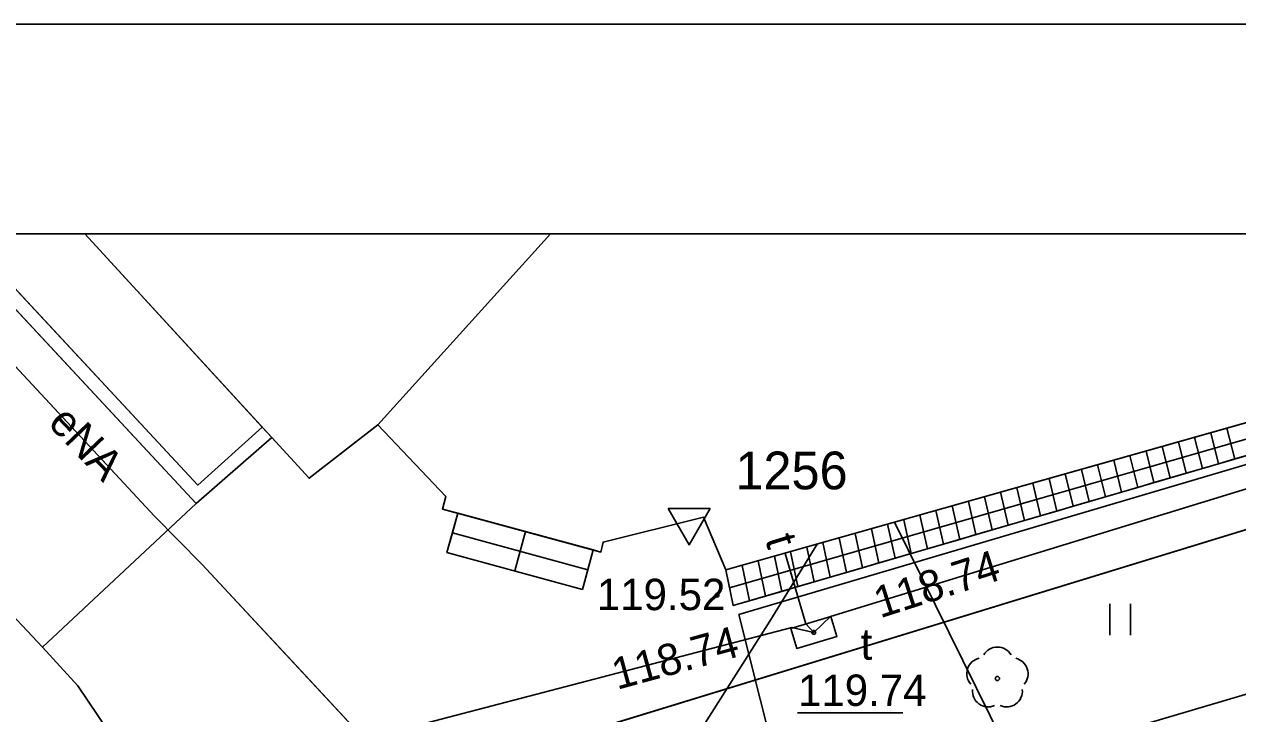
# Model space of a CAD drawing. Extents: x 6432121 to 6432331, y 5662538 to 5662686.
# Drawn here: x 6432164.71 to 6432193.67, y 5662669.6 to 5662686.05 of the extents above; entities that cross this region are included whole.
import ezdxf

# ---------------------------------------------------------------- set-up
doc = ezdxf.new("R2010")
doc.units = 0
for name, color, linetype in [('Warstwa 1', 7, 'Continuous'), ('Warstwa 10', 7, 'Continuous'), ('Warstwa 11', 7, 'Continuous'), ('Warstwa 12', 7, 'Continuous'), ('Warstwa 13', 7, 'Continuous'), ('Warstwa 14', 7, 'Continuous'), ('Warstwa 15', 7, 'Continuous'), ('Warstwa 2', 7, 'Continuous'), ('Warstwa 25', 7, 'Continuous'), ('Warstwa 36', 7, 'Continuous'), ('Warstwa 4', 7, 'Continuous'), ('Warstwa 5', 7, 'Continuous'), ('Warstwa 6', 7, 'Continuous'), ('Warstwa 61', 7, 'Continuous'), ('Warstwa 63', 7, 'Continuous'), ('Warstwa 9', 7, 'Continuous')]:
    doc.layers.add(name, color=color, linetype=linetype)

msp = doc.modelspace()

# ---------------------------------------------------------------- linework, layer by layer
at = {"layer": 'Warstwa 1'}
msp.add_line((6432136.78, 5662656.51), (6432207.04, 5662678.03), dxfattribs=at)
msp.add_line((6432136.78, 5662656.51), (6432207.04, 5662678.03), dxfattribs=at)
msp.add_lwpolyline([(6432166.159, 5662681.053), (6432171.511, 5662675.224), (6432173.15, 5662676.497), (6432174.775, 5662674.789), (6432174.698, 5662674.488), (6432178.474, 5662673.461), (6432178.529, 5662673.7), (6432180.921, 5662674.296), (6432181.459, 5662673.034), (6432202.03, 5662678.854), (6432201.441, 5662681.053)], dxfattribs=at)
at = {"layer": 'Warstwa 10'}
msp.add_lwpolyline([(6432178.835, 5662663.483), (6432175.942, 5662663.535), (6432175.535, 5662666.115), (6432173.894, 5662667.86), (6432171.424, 5662670.517), (6432168.955, 5662673.173), (6432167.819, 5662674.322), (6432163.861, 5662678.574), (6432161.552, 5662681.053)], dxfattribs=at)
at = {"layer": 'Warstwa 11'}
msp.add_circle((6432187.938, 5662670.445), 0.05, dxfattribs=at)
for centre, start, end in [((6432187.938, 5662670.82), 30.1471, 149.8529), ((6432187.581, 5662670.561), 102.1471, 221.8529), ((6432188.295, 5662670.561), 318.1471, 77.8529), ((6432187.718, 5662670.142), 174.1471, 293.8529), ((6432188.158, 5662670.142), 246.1471, 5.8529)]:
    msp.add_arc(centre, 0.375, start, end, dxfattribs=at)
at = {"layer": 'Warstwa 12'}
for points in [[(6432161.551, 5662681.053), (6432167.819, 5662674.322), (6432168.955, 5662673.173), (6432173.894, 5662667.86), (6432175.535, 5662666.115), (6432175.942, 5662663.535), (6432176.507, 5662663.465), (6432178.7, 5662662.668), (6432179.059, 5662662.663), (6432183.548, 5662663.582), (6432184.625, 5662663.866), (6432192.37, 5662666.167), (6432200.892, 5662668.754), (6432210.964, 5662671.473), (6432222.171, 5662674.51), (6432232.177, 5662677.188), (6432233.223, 5662677.473), (6432238.797, 5662677.192), (6432240.154, 5662672.977), (6432241.644, 5662668.194), (6432242.191, 5662665.717), (6432243.645, 5662658.765)], [(6432214.6, 5662681.053), (6432203.235, 5662677.843), (6432183.955, 5662671.923), (6432183.557, 5662671.545)], [(6432191.24, 5662662.505), (6432187.764, 5662669.553), (6432185.483, 5662674.172)], [(6432168.881, 5662650.259), (6432171.042, 5662653.726), (6432174.453, 5662659.119), (6432177.758, 5662664.34), (6432182.508, 5662671.81), (6432183.638, 5662673.65)], [(6432183.557, 5662671.545), (6432183.363, 5662671.751), (6432182.873, 5662673.427)], [(6432183.557, 5662671.545), (6432183.032, 5662671.665), (6432164.195, 5662666.743), (6432152.012, 5662663.254), (6432148.033, 5662662.16), (6432146.555, 5662661.756), (6432145.118, 5662661.304), (6432143.977, 5662660.583), (6432141.306, 5662658.483), (6432136.493, 5662654.9), (6432135.237, 5662654.58)]]:
    msp.add_lwpolyline(points, dxfattribs=at)
at = {"layer": 'Warstwa 14'}
msp.add_line((6432185.68, 5662669.627), (6432183.166, 5662669.627), dxfattribs=at)
msp.add_circle((6432183.557, 5662671.545), 0.045, dxfattribs=at)
msp.add_circle((6432183.557, 5662671.545), 0.045, dxfattribs=at)
msp.add_circle((6432183.557, 5662671.545), 0.045, dxfattribs=at)
msp.add_circle((6432183.557, 5662671.545), 0.045, dxfattribs=at)
at = {"layer": 'Warstwa 2'}
msp.add_lwpolyline([(6432162.823, 5662681.053), (6432168.816, 5662674.622), (6432170.62, 5662676.193), (6432170.39, 5662676.444), (6432168.855, 5662675.061), (6432163.274, 5662681.053)], dxfattribs=at)
at = {"layer": 'Warstwa 25'}
msp.add_circle((6432181.247, 5662672.433), 0.045, dxfattribs=at)
at = {"layer": 'Warstwa 36'}
for p, q in [((6432193.415, 5662676.417), (6432193.603, 5662675.681)), ((6432192.258, 5662676.089), (6432192.445, 5662675.343)), ((6432192.643, 5662676.198), (6432192.831, 5662675.457)), ((6432193.029, 5662676.307), (6432193.217, 5662675.569)), ((6432191.1, 5662675.762), (6432191.287, 5662675.005)), ((6432191.486, 5662675.871), (6432191.672, 5662675.118)), ((6432191.872, 5662675.979), (6432192.059, 5662675.231)), ((6432190.329, 5662675.543), (6432190.514, 5662674.78)), ((6432190.715, 5662675.652), (6432190.9, 5662674.892)), ((6432189.172, 5662675.216), (6432189.356, 5662674.441)), ((6432189.558, 5662675.325), (6432189.742, 5662674.554)), ((6432189.943, 5662675.434), (6432190.128, 5662674.666)), ((6432188.015, 5662674.888), (6432188.198, 5662674.103)), ((6432188.401, 5662674.997), (6432188.583, 5662674.215)), ((6432188.786, 5662675.107), (6432188.97, 5662674.328)), ((6432187.244, 5662674.67), (6432187.425, 5662673.877)), ((6432187.629, 5662674.78), (6432187.811, 5662673.99)), ((6432186.087, 5662674.344), (6432186.267, 5662673.539)), ((6432186.472, 5662674.452), (6432186.653, 5662673.652)), ((6432186.858, 5662674.561), (6432187.039, 5662673.765)), ((6432184.93, 5662674.016), (6432185.109, 5662673.2)), ((6432185.315, 5662674.125), (6432185.494, 5662673.314)), ((6432185.701, 5662674.234), (6432185.88, 5662673.426)), ((6432178.161, 5662673.041), (6432174.93, 5662673.92)), ((6432184.158, 5662673.798), (6432184.336, 5662672.975)), ((6432184.544, 5662673.906), (6432184.722, 5662673.088)), ((6432183.001, 5662673.47), (6432183.178, 5662672.637)), ((6432183.387, 5662673.579), (6432183.564, 5662672.749)), ((6432183.773, 5662673.689), (6432183.95, 5662672.862)), ((6432181.844, 5662673.143), (6432182.02, 5662672.299)), ((6432182.23, 5662673.252), (6432182.406, 5662672.411)), ((6432182.616, 5662673.361), (6432182.791, 5662672.523))]:
    msp.add_line(p, q, dxfattribs=at)
for points in [[(6432181.459, 5662673.034), (6432201.9, 5662678.817), (6432202.099, 5662678.163), (6432181.633, 5662672.186)], [(6432175.058, 5662674.39), (6432174.802, 5662673.45), (6432178.034, 5662672.57), (6432178.289, 5662673.511)]]:
    msp.add_lwpolyline(points, close=True, dxfattribs=at)
at = {"layer": 'Warstwa 4'}
msp.add_lwpolyline([(6432201.441, 5662681.053), (6432202.03, 5662678.854), (6432181.459, 5662673.034), (6432180.921, 5662674.296), (6432178.529, 5662673.7), (6432178.474, 5662673.461), (6432174.698, 5662674.488), (6432174.775, 5662674.789), (6432173.15, 5662676.497), (6432177.276, 5662681.053)], dxfattribs=at)
msp.add_lwpolyline([(6432183.965, 5662671.927), (6432183.006, 5662671.642), (6432183.149, 5662671.163), (6432184.108, 5662671.448)], close=True, dxfattribs=at)
at = {"layer": 'Warstwa 5'}
for p, q in [((6432155.849, 5662681.053), (6432165.149, 5662671.191)), ((6432181.767, 5662671.976), (6432202.15, 5662677.993)), ((6432181.767, 5662671.976), (6432183.048, 5662666.886)), ((6432190.617, 5662671.478), (6432190.617, 5662672.228)), ((6432191.117, 5662671.478), (6432191.117, 5662672.228)), ((6432165.149, 5662671.191), (6432165.991, 5662670.272)), ((6432183.048, 5662666.886), (6432197.24, 5662671.06)), ((6432165.991, 5662670.272), (6432166.712, 5662669.195))]:
    msp.add_line(p, q, dxfattribs=at)
at = {"layer": 'Warstwa 6'}
for points in [[(6432139.86, 5662681.053), (6432132.84, 5662660.45), (6432136.78, 5662656.51), (6432207.04, 5662678.03), (6432217.416, 5662681.053)], [(6432217.416, 5662681.053), (6432207.04, 5662678.03), (6432136.78, 5662656.51), (6432134.43, 5662655.74), (6432136.954, 5662653.004), (6432164.325, 5662660.371), (6432183.398, 5662664.76), (6432232.544, 5662677.413), (6432235.366, 5662681.053)]]:
    msp.add_lwpolyline(points, dxfattribs=at)
at = {"layer": 'Warstwa 61'}
for points in [[(6432202, 5662678.49), (6432181.546, 5662672.61)], [(6432176.418, 5662673.01), (6432176.674, 5662673.951)]]:
    msp.add_lwpolyline(points, dxfattribs=at)
at = {"layer": 'Warstwa 63'}
msp.add_line((6432166.088, 5662681.052), (6432166.086, 5662681.053), dxfattribs=at)
msp.add_line((6432166.088, 5662681.052), (6432166.086, 5662681.053), dxfattribs=at)
for points in [[(6432120.976, 5662686.053), (6432330.976, 5662686.053), (6432330.976, 5662537.553), (6432120.976, 5662537.553)], [(6432125.976, 5662556.053), (6432325.976, 5662556.053), (6432325.976, 5662681.053), (6432125.976, 5662681.053)]]:
    msp.add_lwpolyline(points, close=True, dxfattribs=at)
at = {"layer": 'Warstwa 9'}
for p, q in [((6432155.849, 5662681.053), (6432165.149, 5662671.191)), ((6432162.823, 5662681.053), (6432168.816, 5662674.622)), ((6432163.274, 5662681.053), (6432168.855, 5662675.061)), ((6432166.158, 5662681.053), (6432170.39, 5662676.444)), ((6432181.767, 5662671.976), (6432202.15, 5662677.993)), ((6432168.855, 5662675.061), (6432170.39, 5662676.444)), ((6432171.511, 5662675.224), (6432173.15, 5662676.497)), ((6432173.15, 5662676.497), (6432174.775, 5662674.789)), ((6432168.816, 5662674.622), (6432170.62, 5662676.193)), ((6432170.62, 5662676.193), (6432171.511, 5662675.224)), ((6432193.603, 5662675.682), (6432193.99, 5662675.795)), ((6432192.445, 5662675.344), (6432192.831, 5662675.456)), ((6432192.831, 5662675.456), (6432193.217, 5662675.569)), ((6432193.217, 5662675.569), (6432193.603, 5662675.682)), ((6432191.672, 5662675.118), (6432192.059, 5662675.231)), ((6432192.059, 5662675.231), (6432192.445, 5662675.344)), ((6432190.514, 5662674.78), (6432190.9, 5662674.892)), ((6432190.9, 5662674.892), (6432191.287, 5662675.005)), ((6432191.287, 5662675.005), (6432191.672, 5662675.118)), ((6432165.149, 5662671.191), (6432168.816, 5662674.622)), ((6432165.149, 5662671.191), (6432168.816, 5662674.622)), ((6432174.698, 5662674.488), (6432174.775, 5662674.789)), ((6432189.742, 5662674.554), (6432190.128, 5662674.667)), ((6432190.128, 5662674.667), (6432190.514, 5662674.78)), ((6432174.698, 5662674.488), (6432175.058, 5662674.39)), ((6432174.93, 5662673.92), (6432175.058, 5662674.39)), ((6432178.529, 5662673.7), (6432180.921, 5662674.296)), ((6432180.921, 5662674.296), (6432181.459, 5662673.034)), ((6432188.583, 5662674.216), (6432188.97, 5662674.329)), ((6432188.97, 5662674.329), (6432189.356, 5662674.441)), ((6432189.356, 5662674.441), (6432189.742, 5662674.554)), ((6432187.811, 5662673.99), (6432188.198, 5662674.103)), ((6432188.198, 5662674.103), (6432188.583, 5662674.216)), ((6432174.802, 5662673.45), (6432174.93, 5662673.92)), ((6432186.653, 5662673.652), (6432187.039, 5662673.765)), ((6432187.039, 5662673.765), (6432187.425, 5662673.877)), ((6432187.425, 5662673.877), (6432187.811, 5662673.99)), ((6432174.802, 5662673.45), (6432178.034, 5662672.57)), ((6432178.162, 5662673.041), (6432178.289, 5662673.511)), ((6432178.289, 5662673.511), (6432178.474, 5662673.461)), ((6432178.474, 5662673.461), (6432178.529, 5662673.7)), ((6432185.494, 5662673.314), (6432185.88, 5662673.426)), ((6432185.88, 5662673.426), (6432186.267, 5662673.539)), ((6432186.267, 5662673.539), (6432186.653, 5662673.652)), ((6432184.722, 5662673.088), (6432185.109, 5662673.201)), ((6432185.109, 5662673.201), (6432185.494, 5662673.314)), ((6432178.034, 5662672.57), (6432178.162, 5662673.041)), ((6432181.459, 5662673.034), (6432181.633, 5662672.186)), ((6432183.564, 5662672.75), (6432183.95, 5662672.863)), ((6432183.95, 5662672.863), (6432184.336, 5662672.975)), ((6432184.336, 5662672.975), (6432184.722, 5662673.088)), ((6432182.791, 5662672.524), (6432183.178, 5662672.637)), ((6432183.178, 5662672.637), (6432183.564, 5662672.75)), ((6432181.633, 5662672.186), (6432182.02, 5662672.299)), ((6432182.02, 5662672.299), (6432182.406, 5662672.412)), ((6432182.406, 5662672.412), (6432182.791, 5662672.524)), ((6432181.767, 5662671.976), (6432183.048, 5662666.886)), ((6432165.149, 5662671.191), (6432165.991, 5662670.272)), ((6432183.048, 5662666.886), (6432197.24, 5662671.06)), ((6432165.991, 5662670.272), (6432166.712, 5662669.195))]:
    msp.add_line(p, q, dxfattribs=at)
msp.add_lwpolyline([(6432180.081, 5662674.5), (6432181.081, 5662674.5), (6432180.581, 5662673.634)], close=True, dxfattribs=at)

# ---------------------------------------------------------------- texts
at = {"layer": 'Warstwa 10'}
msp.add_text('1256', height=0.9, dxfattribs=at).set_placement((6432181.685, 5662674.959))
at = {"layer": 'Warstwa 13'}
for s, rotation, p in [('eNA', 313.66, (6432165.252, 5662676.514)), ('t', 286.9831, (6432182.387, 5662673.765))]:
    msp.add_text(s, height=0.75, rotation=rotation, dxfattribs=at).set_placement(p)
at = {"layer": 'Warstwa 14'}
for rotation, p in [(17.7674, (6432185.138, 5662671.878)), (15.3381, (6432178.861, 5662670.172))]:
    msp.add_text('118.74', height=0.75, rotation=rotation, dxfattribs=at).set_placement(p)
at = {"layer": 'Warstwa 15'}
msp.add_text('119.74', height=0.75, dxfattribs=at).set_placement((6432183.179, 5662669.79))
at = {"layer": 'Warstwa 25'}
msp.add_text('119.52', height=0.75, dxfattribs=at).set_placement((6432178.378, 5662672.076))
at = {"layer": 'Warstwa 5'}
msp.add_text('t', height=0.75, dxfattribs=at).set_placement((6432184.673, 5662670.893))

doc.saveas('drawing.dxf')
